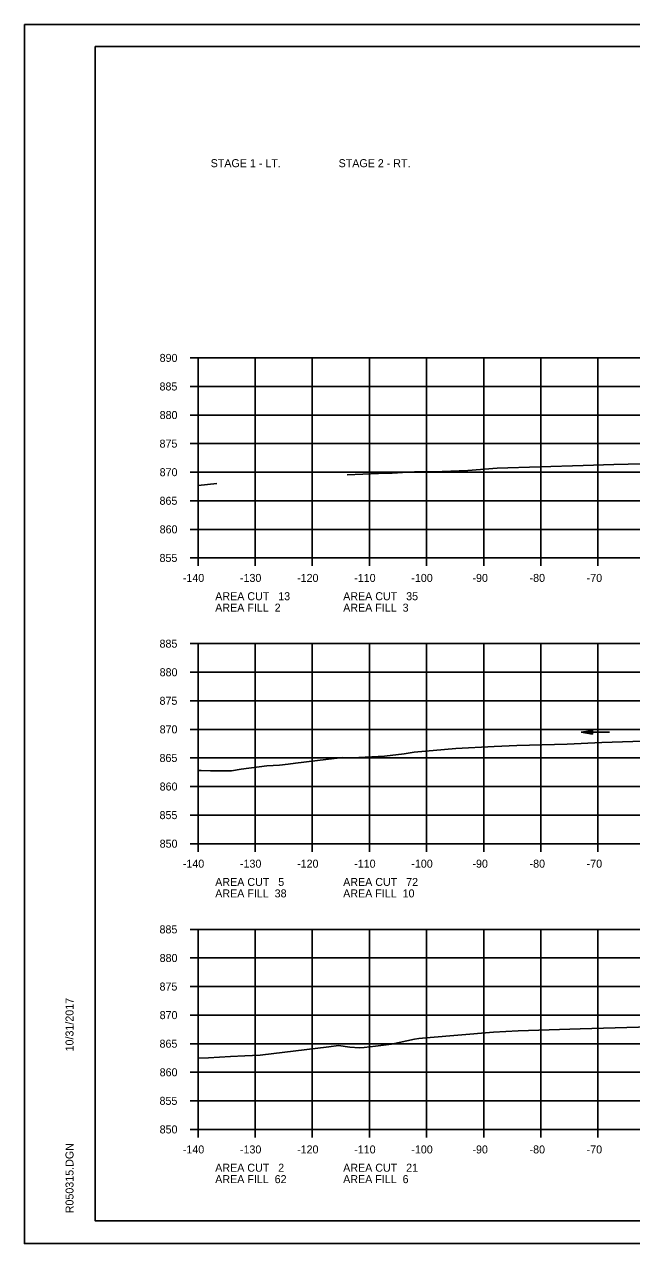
# Model space of a CAD drawing. Extents: x 1486524 to 1499135, y 326561 to 337924.
# Drawn here: x 1488812.5 to 1488918.8, y 334486 to 334699.3 of the extents above; entities that cross this region are included whole.
import ezdxf

# ---------------------------------------------------------------- set-up
doc = ezdxf.new("R2010")
doc.units = 0
for name, color, linetype in [('Default', 7, 'Continuous'), ('E_Const Align', 7, 'Continuous'), ('E_Const Align Station', 7, 'Continuous'), ('E_Ownership Information', 7, 'Continuous'), ('E_Property Line', 7, 'Continuous'), ('E_Proposed ROW Fig Annot', 7, 'Continuous'), ('E_Quarter Calls', 7, 'Continuous'), ('E_Tract Number', 7, 'Continuous'), ('R_Water Annot', 7, 'Continuous')]:
    doc.layers.add(name, color=color, linetype=linetype)

msp = doc.modelspace()

# ---------------------------------------------------------------- linework, layer by layer
at = {"layer": 'E_Const Align'}
for p, q in [((1488841.49, 334640.99), (1488842.89, 334640.99)), ((1488842.89, 334605.99), (1488842.89, 334640.99)), ((1488841.49, 334635.99), (1488842.89, 334635.99)), ((1488841.49, 334630.99), (1488842.89, 334630.99)), ((1488841.49, 334625.99), (1488842.89, 334625.99)), ((1488841.49, 334620.99), (1488842.89, 334620.99)), ((1488841.49, 334615.99), (1488842.89, 334615.99)), ((1488841.49, 334610.99), (1488842.89, 334610.99)), ((1488841.49, 334605.99), (1488842.89, 334605.99)), ((1488842.89, 334605.99), (1489122.89, 334605.99)), ((1488842.89, 334604.59), (1488842.89, 334605.99)), ((1488852.89, 334604.59), (1488852.89, 334605.99)), ((1488862.89, 334604.59), (1488862.89, 334605.99)), ((1488872.89, 334604.59), (1488872.89, 334605.99)), ((1488882.89, 334604.59), (1488882.89, 334605.99)), ((1488892.89, 334604.59), (1488892.89, 334605.99)), ((1488902.89, 334604.59), (1488902.89, 334605.99)), ((1488912.89, 334604.59), (1488912.89, 334605.99)), ((1488841.49, 334590.99), (1488842.89, 334590.99)), ((1488842.89, 334555.99), (1488842.89, 334590.99)), ((1488841.49, 334585.99), (1488842.89, 334585.99)), ((1488841.49, 334580.99), (1488842.89, 334580.99)), ((1488841.49, 334575.99), (1488842.89, 334575.99)), ((1488841.49, 334570.99), (1488842.89, 334570.99)), ((1488841.49, 334565.99), (1488842.89, 334565.99)), ((1488841.49, 334560.99), (1488842.89, 334560.99)), ((1488841.49, 334555.99), (1488842.89, 334555.99)), ((1488842.89, 334555.99), (1489122.89, 334555.99)), ((1488842.89, 334554.59), (1488842.89, 334555.99)), ((1488852.89, 334554.59), (1488852.89, 334555.99)), ((1488862.89, 334554.59), (1488862.89, 334555.99)), ((1488872.89, 334554.59), (1488872.89, 334555.99)), ((1488882.89, 334554.59), (1488882.89, 334555.99)), ((1488892.89, 334554.59), (1488892.89, 334555.99)), ((1488902.89, 334554.59), (1488902.89, 334555.99)), ((1488912.89, 334554.59), (1488912.89, 334555.99)), ((1488841.49, 334540.99), (1488842.89, 334540.99)), ((1488842.89, 334505.99), (1488842.89, 334540.99)), ((1488841.49, 334535.99), (1488842.89, 334535.99)), ((1488841.49, 334530.99), (1488842.89, 334530.99)), ((1488841.49, 334525.99), (1488842.89, 334525.99)), ((1488841.49, 334520.99), (1488842.89, 334520.99)), ((1488841.49, 334515.99), (1488842.89, 334515.99)), ((1488841.49, 334510.99), (1488842.89, 334510.99)), ((1488841.49, 334505.99), (1488842.89, 334505.99)), ((1488842.89, 334505.99), (1489122.89, 334505.99)), ((1488842.89, 334504.59), (1488842.89, 334505.99)), ((1488852.89, 334504.59), (1488852.89, 334505.99)), ((1488862.89, 334504.59), (1488862.89, 334505.99)), ((1488872.89, 334504.59), (1488872.89, 334505.99)), ((1488882.89, 334504.59), (1488882.89, 334505.99)), ((1488892.89, 334504.59), (1488892.89, 334505.99)), ((1488902.89, 334504.59), (1488902.89, 334505.99)), ((1488912.89, 334504.59), (1488912.89, 334505.99))]:
    msp.add_line(p, q, dxfattribs=at)
at = {"layer": 'E_Ownership Information'}
for p, q in [((1488842.89, 334640.99), (1489122.89, 334640.99)), ((1488842.89, 334605.99), (1488842.89, 334640.99)), ((1488842.89, 334640.99), (1489122.89, 334640.99)), ((1488842.89, 334605.99), (1488842.89, 334640.99)), ((1488852.89, 334605.99), (1488852.89, 334640.99)), ((1488852.89, 334605.99), (1488852.89, 334640.99)), ((1488862.89, 334605.99), (1488862.89, 334640.99)), ((1488862.89, 334605.99), (1488862.89, 334640.99)), ((1488872.89, 334605.99), (1488872.89, 334640.99)), ((1488872.89, 334605.99), (1488872.89, 334640.99)), ((1488882.89, 334605.99), (1488882.89, 334640.99)), ((1488882.89, 334605.99), (1488882.89, 334640.99)), ((1488892.89, 334605.99), (1488892.89, 334640.99)), ((1488892.89, 334605.99), (1488892.89, 334640.99)), ((1488902.89, 334605.99), (1488902.89, 334640.99)), ((1488902.89, 334605.99), (1488902.89, 334640.99)), ((1488912.89, 334605.99), (1488912.89, 334640.99)), ((1488912.89, 334605.99), (1488912.89, 334640.99)), ((1488842.89, 334635.99), (1489122.89, 334635.99)), ((1488842.89, 334635.99), (1489122.89, 334635.99)), ((1488842.89, 334630.99), (1489122.89, 334630.99)), ((1488842.89, 334630.99), (1489122.89, 334630.99)), ((1488842.89, 334625.99), (1489122.89, 334625.99)), ((1488842.89, 334625.99), (1489122.89, 334625.99)), ((1488842.89, 334620.99), (1489122.89, 334620.99)), ((1488842.89, 334620.99), (1489122.89, 334620.99)), ((1488842.89, 334615.99), (1489122.89, 334615.99)), ((1488842.89, 334615.99), (1489122.89, 334615.99)), ((1488842.89, 334610.99), (1489122.89, 334610.99)), ((1488842.89, 334610.99), (1489122.89, 334610.99)), ((1488842.89, 334605.99), (1489122.89, 334605.99)), ((1488842.89, 334605.99), (1489122.89, 334605.99)), ((1488842.89, 334590.99), (1489122.89, 334590.99)), ((1488842.89, 334555.99), (1488842.89, 334590.99)), ((1488852.89, 334555.99), (1488852.89, 334590.99)), ((1488862.89, 334555.99), (1488862.89, 334590.99)), ((1488872.89, 334555.99), (1488872.89, 334590.99)), ((1488882.89, 334555.99), (1488882.89, 334590.99)), ((1488892.89, 334555.99), (1488892.89, 334590.99)), ((1488902.89, 334555.99), (1488902.89, 334590.99)), ((1488912.89, 334555.99), (1488912.89, 334590.99)), ((1488842.89, 334585.99), (1489122.89, 334585.99)), ((1488842.89, 334580.99), (1489122.89, 334580.99)), ((1488842.89, 334575.99), (1489122.89, 334575.99)), ((1488842.89, 334570.99), (1489122.89, 334570.99)), ((1488842.89, 334565.99), (1489122.89, 334565.99)), ((1488842.89, 334560.99), (1489122.89, 334560.99)), ((1488842.89, 334555.99), (1489122.89, 334555.99)), ((1488842.89, 334540.99), (1489122.89, 334540.99)), ((1488842.89, 334505.99), (1488842.89, 334540.99)), ((1488852.89, 334505.99), (1488852.89, 334540.99)), ((1488862.89, 334505.99), (1488862.89, 334540.99)), ((1488872.89, 334505.99), (1488872.89, 334540.99)), ((1488882.89, 334505.99), (1488882.89, 334540.99)), ((1488892.89, 334505.99), (1488892.89, 334540.99)), ((1488902.89, 334505.99), (1488902.89, 334540.99)), ((1488912.89, 334505.99), (1488912.89, 334540.99)), ((1488842.89, 334535.99), (1489122.89, 334535.99)), ((1488842.89, 334530.99), (1489122.89, 334530.99)), ((1488842.89, 334525.99), (1489122.89, 334525.99)), ((1488842.89, 334520.99), (1489122.89, 334520.99)), ((1488842.89, 334515.99), (1489122.89, 334515.99)), ((1488842.89, 334510.99), (1489122.89, 334510.99)), ((1488842.89, 334505.99), (1489122.89, 334505.99))]:
    msp.add_line(p, q, dxfattribs=at)
at = {"layer": 'E_Property Line'}
for p, q in [((1488824.89, 334695.45), (1489141.07, 334695.45)), ((1488824.89, 334489.99), (1488824.89, 334695.45)), ((1488824.89, 334489.99), (1488824.89, 334489.99)), ((1489141.07, 334489.99), (1488824.89, 334489.99))]:
    msp.add_line(p, q, dxfattribs=at)
at = {"layer": 'E_Proposed ROW Fig Annot'}
for p, q in [((1488911.93, 334575.78), (1488909.93, 334575.48)), ((1488911.93, 334575.18), (1488909.93, 334575.48)), ((1488911.93, 334575.73), (1488910.26, 334575.48)), ((1488911.93, 334575.23), (1488910.26, 334575.48)), ((1488911.93, 334575.68), (1488910.6, 334575.48)), ((1488911.93, 334575.28), (1488910.6, 334575.48)), ((1488911.93, 334575.63), (1488910.94, 334575.48)), ((1488911.93, 334575.33), (1488910.94, 334575.48)), ((1488911.93, 334575.58), (1488911.28, 334575.48)), ((1488911.93, 334575.38), (1488911.28, 334575.48)), ((1488911.93, 334575.52), (1488911.61, 334575.48)), ((1488911.93, 334575.43), (1488911.61, 334575.48)), ((1488911.93, 334575.18), (1488911.93, 334575.78))]:
    msp.add_line(p, q, dxfattribs=at)
at = {"layer": 'E_Quarter Calls'}
for p, q in [((1488812.48, 334699.35), (1489145.82, 334699.35)), ((1488812.48, 334486.01), (1489145.82, 334486.01))]:
    msp.add_line(p, q, dxfattribs=at)
for points in [[(1488812.48, 334699.35), (1489145.82, 334699.35), (1489145.82, 334486.01), (1488812.48, 334486.01)], [(1489058.81, 334695.45), (1489058.81, 334685.57), (1489094.54, 334685.57), (1489094.54, 334682.65), (1489117.74, 334682.65), (1489117.74, 334658.32), (1489141.07, 334658.32), (1489141.07, 334489.99), (1488824.89, 334489.99), (1488824.89, 334695.45)]]:
    msp.add_lwpolyline(points, close=True, dxfattribs=at)
at = {"layer": 'E_Tract Number'}
for points in [[(1488869.01, 334620.54), (1488874.5, 334620.74), (1488876.89, 334620.84), (1488879.58, 334621.01), (1488880.76, 334621.08), (1488884.11, 334621.04), (1488890.12, 334621.29), (1488895.26, 334621.67), (1488910.28, 334622.19), (1488915.66, 334622.32), (1488930.84, 334622.69)], [(1488842.89, 334618.68), (1488846.16, 334619.02)], [(1488842.89, 334568.77), (1488843.42, 334568.82), (1488845.09, 334568.76), (1488848.71, 334568.74), (1488850.44, 334569.02), (1488854.9, 334569.61), (1488857.12, 334569.74), (1488858.66, 334569.92), (1488859.97, 334570.07), (1488865.24, 334570.73), (1488868.22, 334571.07), (1488869.93, 334571.02), (1488875.53, 334571.33), (1488878.99, 334571.71), (1488880.74, 334571.99), (1488888.02, 334572.63), (1488894.72, 334573.01), (1488898.67, 334573.17), (1488907.5, 334573.43), (1488913.55, 334573.7), (1488920.78, 334573.91)], [(1488842.89, 334518.45), (1488844.74, 334518.52), (1488848.56, 334518.78), (1488851.09, 334518.84), (1488853.74, 334518.99), (1488865.78, 334520.46), (1488867.45, 334520.65), (1488869.43, 334520.4), (1488871.17, 334520.25), (1488871.98, 334520.34), (1488873.93, 334520.55), (1488876.75, 334520.93), (1488880.79, 334521.77), (1488881.54, 334521.89), (1488882.83, 334521.99), (1488894.61, 334523.01), (1488898.92, 334523.25), (1488909.8, 334523.58), (1488913.88, 334523.69), (1488922.03, 334523.94)]]:
    msp.add_lwpolyline(points, dxfattribs=at)
at = {"layer": 'R_Water Annot'}
msp.add_line((1488909.93, 334575.48), (1488914.93, 334575.48), dxfattribs=at)

# ---------------------------------------------------------------- texts
at = {"layer": 'Default'}
for s, p in [('STAGE 1 - LT.', (1488845.09, 334674.36)), ('STAGE 2 - RT.', (1488867.49, 334674.36))]:
    msp.add_text(s, height=1.4, dxfattribs=at).set_placement(p)
at = {"layer": 'E_Const Align Station'}
for s, p in [('890', (1488836.16, 334640.29)), ('885', (1488836.14, 334635.29)), ('880', (1488836.16, 334630.29)), ('875', (1488836.14, 334625.29)), ('870', (1488836.16, 334620.29)), ('865', (1488836.14, 334615.29)), ('860', (1488836.16, 334610.29)), ('855', (1488836.14, 334605.29)), ('-140', (1488840.22, 334601.79)), ('-130', (1488850.22, 334601.79)), ('-120', (1488860.22, 334601.79)), ('-110', (1488870.22, 334601.79)), ('-100', (1488880.22, 334601.79)), ('-90', (1488890.92, 334601.79)), ('-80', (1488900.92, 334601.79)), ('-70', (1488910.92, 334601.79)), ('AREA CUT   13', (1488845.89, 334598.59)), ('AREA CUT   35', (1488868.29, 334598.59)), ('AREA FILL  2', (1488845.89, 334596.59)), ('AREA FILL  3', (1488868.29, 334596.59)), ('885', (1488836.14, 334590.29)), ('880', (1488836.16, 334585.29)), ('875', (1488836.14, 334580.29)), ('870', (1488836.16, 334575.29)), ('865', (1488836.14, 334570.29)), ('860', (1488836.16, 334565.29)), ('855', (1488836.14, 334560.29)), ('850', (1488836.16, 334555.29)), ('-140', (1488840.22, 334551.79)), ('-130', (1488850.22, 334551.79)), ('-120', (1488860.22, 334551.79)), ('-110', (1488870.22, 334551.79)), ('-100', (1488880.22, 334551.79)), ('-90', (1488890.92, 334551.79)), ('-80', (1488900.92, 334551.79)), ('-70', (1488910.92, 334551.79)), ('AREA CUT   5', (1488845.89, 334548.59)), ('AREA CUT   72', (1488868.29, 334548.59)), ('AREA FILL  38', (1488845.89, 334546.59)), ('AREA FILL  10', (1488868.29, 334546.59)), ('885', (1488836.14, 334540.29)), ('880', (1488836.16, 334535.29)), ('875', (1488836.14, 334530.29)), ('870', (1488836.16, 334525.29)), ('865', (1488836.14, 334520.29)), ('860', (1488836.16, 334515.29)), ('855', (1488836.14, 334510.29)), ('850', (1488836.16, 334505.29)), ('-140', (1488840.22, 334501.79)), ('-130', (1488850.22, 334501.79)), ('-120', (1488860.22, 334501.79)), ('-110', (1488870.22, 334501.79)), ('-100', (1488880.22, 334501.79)), ('-90', (1488890.92, 334501.79)), ('-80', (1488900.92, 334501.79)), ('-70', (1488910.92, 334501.79)), ('AREA CUT   2', (1488845.89, 334498.59)), ('AREA CUT   21', (1488868.29, 334498.59)), ('AREA FILL  62', (1488845.89, 334496.59)), ('AREA FILL  6', (1488868.29, 334496.59))]:
    msp.add_text(s, height=1.4, dxfattribs=at).set_placement(p)
at = {"layer": 'E_Property Line'}
for s, p in [('10/31/2017', (1488821.08, 334519.64)), ('R050315.DGN', (1488821.08, 334491.32))]:
    msp.add_text(s, height=1.4, rotation=90, dxfattribs=at).set_placement(p)

doc.saveas('drawing.dxf')
